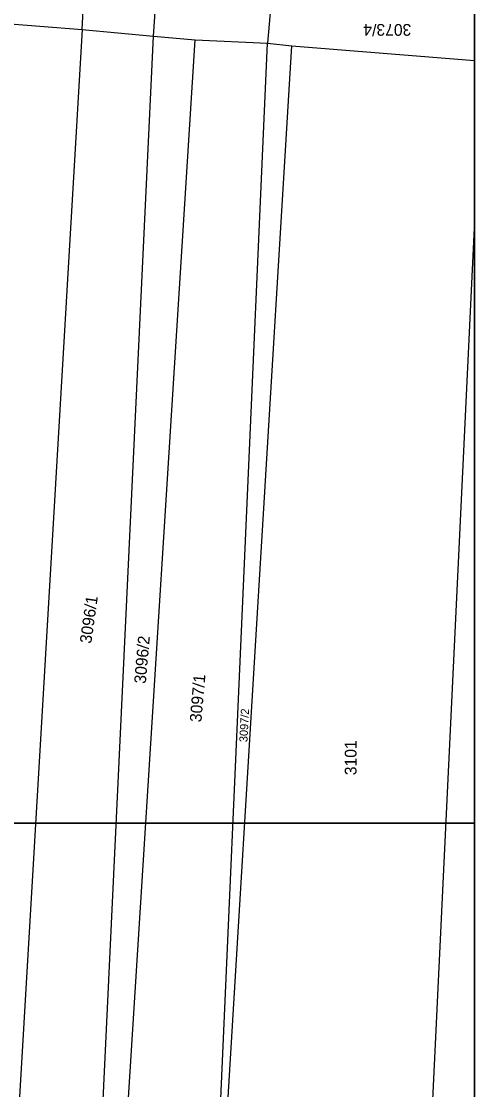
# Model space of a CAD drawing. Extents: x -534410 to -534262, y -1190162 to -1189584.
# Drawn here: x -534294.5 to -534261.6, y -1190023.8 to -1189946.4 of the extents above; entities that cross this region are included whole.
import ezdxf

# ---------------------------------------------------------------- set-up
doc = ezdxf.new("R2010")
doc.units = 0
for name, color, linetype in [('_rámeček', 7, 'Continuous'), ('_rámeček_mřížka', 7, 'Continuous'), ('Hranice parcel', 7, 'Continuous'), ('Parcelní čísla', 7, 'Continuous')]:
    doc.layers.add(name, color=color, linetype=linetype)

msp = doc.modelspace()

# ---------------------------------------------------------------- linework, layer by layer
at = {"layer": '_rámeček'}
msp.add_lwpolyline([(-534410.126, -1190161.97), (-534261.626, -1190161.97), (-534261.626, -1189584.47)], dxfattribs=at)
for points in [[(-534410.126, -1189899.47), (-534261.626, -1189899.47), (-534261.626, -1190004.47), (-534410.126, -1190004.47)], [(-534410.126, -1190004.47), (-534261.626, -1190004.47), (-534261.626, -1190109.47), (-534410.126, -1190109.47)]]:
    msp.add_lwpolyline(points, close=True, dxfattribs=at)
at = {"layer": '_rámeček_mřížka'}
msp.add_line((-534264.626, -1190004.47), (-534261.626, -1190004.47), dxfattribs=at)
msp.add_lwpolyline([(-534410.126, -1190161.97), (-534261.626, -1190161.97), (-534261.626, -1189584.47)], dxfattribs=at)
at = {"layer": 'Hranice parcel'}
for p, q in [((-534290.08, -1189946.94), (-534289.92, -1189943.5)), ((-534284.92, -1189947.42), (-534284.68, -1189943.89)), ((-534276.35, -1189944.53), (-534276.65, -1189947.93)), ((-534290.08, -1189946.94), (-534297.41, -1190071.61)), ((-534297.16, -1189946.38), (-534290.08, -1189946.94)), ((-534290.08, -1189946.94), (-534284.92, -1189947.42)), ((-534291.17, -1190079.8), (-534284.92, -1189947.42)), ((-534290.2, -1190079.83), (-534281.9, -1189947.69)), ((-534284.92, -1189947.42), (-534281.9, -1189947.69)), ((-534281.9, -1189947.69), (-534276.65, -1189947.93)), ((-534281.42, -1190056.27), (-534276.65, -1189947.93)), ((-534281.42, -1190056.27), (-534274.89, -1189948.14)), ((-534276.65, -1189947.93), (-534274.89, -1189948.14)), ((-534274.89, -1189948.14), (-534261.626, -1189949.186)), ((-534261.626, -1189960.811), (-534266.24, -1190056.9))]:
    msp.add_line(p, q, dxfattribs=at)

# ---------------------------------------------------------------- texts
at = {"layer": 'Parcelní čísla'}
for s, height, rotation, p in [('3073/4', 0.85, 180, (-534266.219, -1189946.551)), ('3096/1', 0.85, 82, (-534289.425, -1189991.492)), ('3096/2', 0.85, 85, (-534285.475, -1189994.393)), ('3097/1', 0.85, 85, (-534281.445, -1189997.184)), ('3097/2', 0.595, 87, (-534278.103, -1189998.614)), ('3101', 0.85, 90, (-534270.191, -1190000.999))]:
    msp.add_text(s, height=height, rotation=rotation, dxfattribs=at).set_placement(p)

doc.saveas('drawing.dxf')
